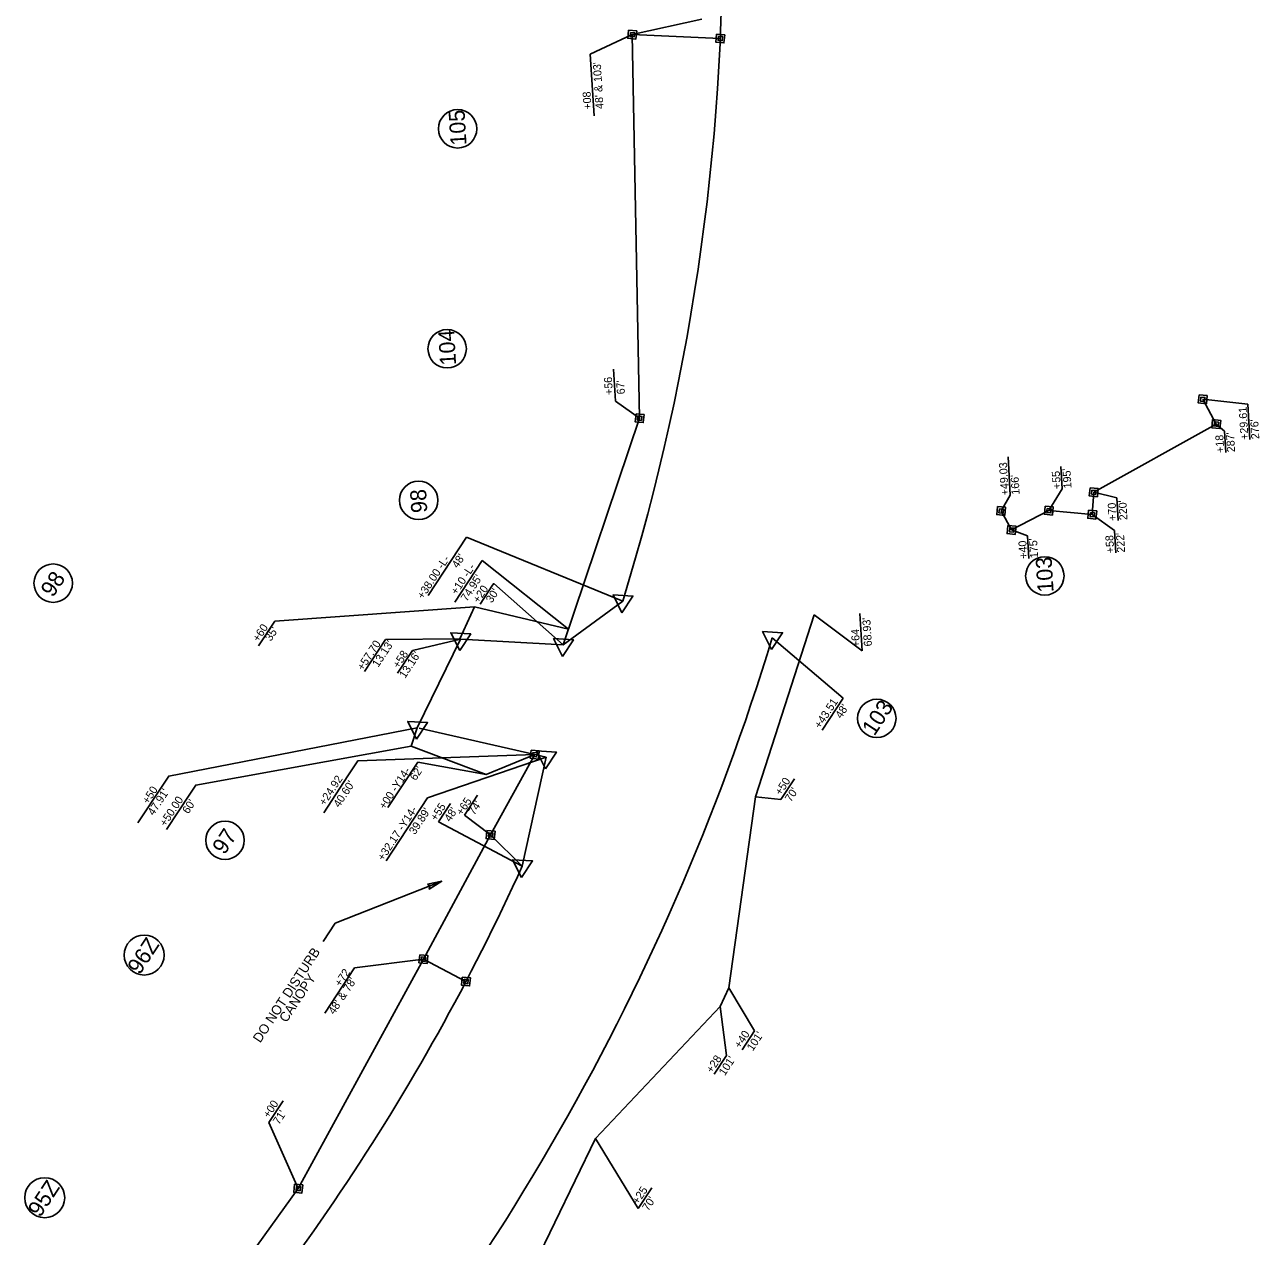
# Model space of a CAD drawing. Extents: x 2320946 to 2332748, y 597838 to 612698.
# Drawn here: x 2327953 to 2328724, y 603619 to 604376 of the extents above; entities that cross this region are included whole.
import ezdxf

# ---------------------------------------------------------------- set-up
doc = ezdxf.new("R2010")
doc.units = 0
for name, color, linetype in [('Prop DSN Text', 7, 'Continuous'), ('Prop Easement Aerial Utility', 7, 'Continuous'), ('Prop Easement Construction', 7, 'Continuous'), ('Prop Easement Construction Station Offsets', 7, 'Continuous'), ('Prop Easement Permanent Drainage Utility', 7, 'Continuous'), ('Prop Easement Permanent Utility', 7, 'Continuous'), ('Prop Easement Permanent Utility Station Offsets', 7, 'Continuous'), ('Prop Parcel Number CELL', 7, 'Continuous'), ('Prop ROW Marker CELL', 7, 'Continuous'), ('Prop ROW Permanent Easement CELL', 7, 'Continuous'), ('Prop ROW RW Lines', 7, 'Continuous'), ('Prop ROW Station Offsets', 7, 'Continuous'), ('Prop Terminator CELL', 7, 'Continuous')]:
    doc.layers.add(name, color=color, linetype=linetype)

msp = doc.modelspace()

# ---------------------------------------------------------------- linework, layer by layer
at = {"layer": 'Prop DSN Text'}
for p, q in [((2328146.87, 603814.88), (2328213.37, 603840.98)), ((2328139.33, 603803.41), (2328146.87, 603814.88))]:
    msp.add_line(p, q, dxfattribs=at)
at = {"layer": 'Prop Easement Aerial Utility'}
msp.add_line((2328201.91, 603792.36), (2328243.88, 603869.93), dxfattribs=at)
at = {"layer": 'Prop Easement Construction'}
for p, q in [((2328332.38, 604369.84), (2328375.8, 604379.44)), ((2328233.88, 604012.39), (2328224.76, 603992.38)), ((2328233.88, 604012.39), (2328292.54, 603998.53)), ((2328409.26, 603893.82), (2328445.89, 604007.5)), ((2328194.27, 603925.47), (2328198.1, 603936.93)), ((2328194.27, 603925.47), (2328241.05, 603907.72)), ((2328241.05, 603907.72), (2328271.47, 603920.11)), ((2328392.7, 603774.46), (2328409.26, 603893.82)), ((2328387.23, 603762.85), (2328392.7, 603774.46)), ((2328309.42, 603680.4), (2328387.23, 603762.85)), ((2328257.65, 603573.86), (2328309.42, 603680.4))]:
    msp.add_line(p, q, dxfattribs=at)
at = {"layer": 'Prop Easement Construction Station Offsets'}
for p, q in [((2328238.61, 604041.37), (2328221.52, 604015.4)), ((2328292.54, 603998.53), (2328238.61, 604041.37)), ((2328233.88, 604012.39), (2328109.15, 604003.51)), ((2328109.15, 604003.51), (2328098.97, 603988.03)), ((2328475.99, 603984.89), (2328445.89, 604007.5)), ((2328474.58, 604008.32), (2328475.99, 603984.89)), ((2328178.33, 603992.05), (2328165.11, 603971.96)), ((2328198.36, 603915.49), (2328179.63, 603887.01)), ((2328198.36, 603915.49), (2328241.05, 603907.72)), ((2328433.73, 603905.01), (2328425.24, 603892.11)), ((2328056, 603895.49), (2328041.39, 603873.28)), ((2328425.24, 603892.11), (2328409.26, 603893.82)), ((2328408.72, 603747.6), (2328400.94, 603735.77)), ((2328391.23, 603732.21), (2328383.54, 603720.51)), ((2328336.13, 603636.65), (2328309.42, 603680.4)), ((2328344.61, 603649.55), (2328336.13, 603636.65))]:
    msp.add_line(p, q, dxfattribs=at)
for points in [[(2328178.33, 603992.05), (2328224.76, 603992.38)], [(2328056, 603895.49), (2328059.71, 603901.13), (2328194.27, 603925.47)], [(2328408.72, 603747.6), (2328392.7, 603774.46)], [(2328391.23, 603732.21), (2328387.23, 603762.85)]]:
    msp.add_lwpolyline(points, dxfattribs=at)
at = {"layer": 'Prop Easement Permanent Drainage Utility'}
for p, q in [((2328123.77, 603649.06), (2328201.91, 603792.36)), ((2328228.48, 603778.43), (2328201.91, 603792.36)), ((2328030.98, 603521), (2328123.77, 603649.06))]:
    msp.add_line(p, q, dxfattribs=at)
at = {"layer": 'Prop Easement Permanent Utility'}
for p, q in [((2328336.98, 604130.26), (2328332.38, 604369.84)), ((2328332.38, 604369.84), (2328387.33, 604367.42)), ((2328697.11, 604126.56), (2328688.64, 604142.1)), ((2328321.81, 604140.81), (2328336.98, 604130.26)), ((2328289.2, 603988.62), (2328336.98, 604130.26)), ((2328620.61, 604083.97), (2328697.11, 604126.56)), ((2328619.65, 604070.03), (2328620.61, 604083.97)), ((2328569.29, 604060.46), (2328562.78, 604072.31)), ((2328592.54, 604072.51), (2328569.29, 604060.46)), ((2328592.54, 604072.51), (2328619.65, 604070.03)), ((2328243.88, 603869.93), (2328271.47, 603920.11))]:
    msp.add_line(p, q, dxfattribs=at)
at = {"layer": 'Prop Easement Permanent Utility Station Offsets'}
for p, q in [((2328332.38, 604369.84), (2328306.15, 604357.53)), ((2328306.15, 604357.53), (2328308.46, 604319.05)), ((2328320.6, 604160.92), (2328321.81, 604140.81)), ((2328716.81, 604139.11), (2328718.14, 604116.94)), ((2328702.21, 604122.19), (2328703.02, 604108.77)), ((2328567.03, 604106.04), (2328568.46, 604082.26)), ((2328600.05, 604100.18), (2328600.89, 604086.2)), ((2328634.94, 604080.47), (2328635.79, 604066.34)), ((2328579.17, 604056.79), (2328580.02, 604042.65)), ((2328633.47, 604060.15), (2328634.31, 604046.09)), ((2328154.76, 603906.85), (2328139.62, 603883.83)), ((2328235.69, 603894.82), (2328227.51, 603882.38)), ((2328243.88, 603869.93), (2328227.51, 603882.38)), ((2328263.68, 603850.54), (2328243.88, 603869.93)), ((2328158.88, 603786.86), (2328140.36, 603758.71)), ((2328201.91, 603792.36), (2328158.88, 603786.86)), ((2328114.34, 603703.97), (2328105.38, 603690.35)), ((2328123.77, 603649.06), (2328105.38, 603690.35))]:
    msp.add_line(p, q, dxfattribs=at)
for points in [[(2328716.81, 604139.11), (2328688.64, 604142.1)], [(2328702.21, 604122.19), (2328697.11, 604126.56)], [(2328568.46, 604082.26), (2328562.78, 604072.31)], [(2328600.89, 604086.2), (2328592.54, 604072.51)], [(2328634.94, 604080.47), (2328620.61, 604083.97)], [(2328633.47, 604060.15), (2328619.65, 604070.03)], [(2328579.17, 604056.79), (2328569.29, 604060.46)], [(2328154.76, 603906.85), (2328160.91, 603916.19), (2328271.47, 603920.11)]]:
    msp.add_lwpolyline(points, dxfattribs=at)
at = {"layer": 'Prop Parcel Number CELL'}
for p, q in [((2328223.27, 604311.01), (2328223.27, 604311.01)), ((2328216.75, 604173.62), (2328216.75, 604173.62)), ((2328198.93, 604078.96), (2328198.93, 604078.96)), ((2327970.68, 604027.21), (2327970.68, 604027.21)), ((2328590.04, 604031.76), (2328590.04, 604031.76)), ((2328485.1, 603942.76), (2328485.1, 603942.76)), ((2328078, 603866.63), (2328078, 603866.63)), ((2328027.51, 603794.93), (2328027.51, 603794.93)), ((2327965.38, 603643.39), (2327965.38, 603643.39))]:
    msp.add_line(p, q, dxfattribs=at)
for centre, radius in [((2328223.27, 604311.01), 12), ((2328216.75, 604173.62), 12), ((2328198.93, 604078.96), 12), ((2328590.04, 604031.76), 12), ((2327970.68, 604027.21), 12), ((2328485.1, 603942.76), 12), ((2328078, 603866.63), 12), ((2328027.51, 603794.93), 12.49), ((2327965.38, 603643.39), 12.49)]:
    msp.add_circle(centre, radius, dxfattribs=at)
at = {"layer": 'Prop ROW Marker CELL'}
for p, q in [((2328332.38, 604369.84), (2328332.38, 604369.84)), ((2328387.33, 604367.42), (2328387.33, 604367.42)), ((2328688.64, 604142.1), (2328688.64, 604142.1)), ((2328336.98, 604130.26), (2328336.98, 604130.26)), ((2328697.11, 604126.56), (2328697.11, 604126.56)), ((2328620.61, 604083.97), (2328620.61, 604083.97)), ((2328562.78, 604072.31), (2328562.78, 604072.31)), ((2328592.54, 604072.51), (2328592.54, 604072.51)), ((2328619.65, 604070.03), (2328619.65, 604070.03)), ((2328569.29, 604060.46), (2328569.29, 604060.46)), ((2328326.37, 604015.88), (2328326.37, 604015.88)), ((2328225.06, 603992.31), (2328225.06, 603992.31)), ((2328289.2, 603988.62), (2328289.2, 603988.62)), ((2328419.76, 603993.02), (2328419.76, 603993.02)), ((2328198.1, 603936.93), (2328198.1, 603936.93)), ((2328271.47, 603920.11), (2328271.47, 603920.11)), ((2328278.58, 603918.5), (2328278.58, 603918.5)), ((2328243.88, 603869.93), (2328243.88, 603869.93)), ((2328263.68, 603850.54), (2328263.68, 603850.54)), ((2328201.91, 603792.36), (2328201.91, 603792.36)), ((2328228.48, 603778.43), (2328228.48, 603778.43)), ((2328123.77, 603649.06), (2328123.77, 603649.06))]:
    msp.add_line(p, q, dxfattribs=at)
for points in [[(2328325.94, 604008.68), (2328320.35, 604019.84), (2328332.81, 604019.12)], [(2328224.63, 603985.11), (2328219.04, 603996.27), (2328231.5, 603995.55)], [(2328419.34, 603985.82), (2328413.75, 603996.97), (2328426.21, 603996.26)], [(2328288.77, 603981.42), (2328283.18, 603992.58), (2328295.64, 603991.87)], [(2328197.68, 603929.73), (2328192.09, 603940.89), (2328204.55, 603940.18)], [(2328278.15, 603911.3), (2328272.56, 603922.46), (2328285.02, 603921.74)], [(2328263.25, 603843.34), (2328257.66, 603854.5), (2328270.12, 603853.78)]]:
    msp.add_lwpolyline(points, close=True, dxfattribs=at)
at = {"layer": 'Prop ROW Permanent Easement CELL'}
for points in [[(2328330.1, 604372.63), (2328335.17, 604372.12), (2328334.65, 604367.05), (2328329.59, 604367.57)], [(2328331.24, 604371.24), (2328333.77, 604370.98), (2328333.52, 604368.45), (2328330.98, 604368.7)], [(2328385.05, 604370.21), (2328390.11, 604369.69), (2328389.6, 604364.63), (2328384.54, 604365.14)], [(2328386.19, 604368.81), (2328388.72, 604368.56), (2328388.46, 604366.02), (2328385.93, 604366.28)], [(2328686.36, 604144.88), (2328691.42, 604144.37), (2328690.91, 604139.31), (2328685.85, 604139.82)], [(2328687.5, 604143.49), (2328690.03, 604143.23), (2328689.77, 604140.7), (2328687.24, 604140.96)], [(2328334.71, 604133.05), (2328339.77, 604132.54), (2328339.26, 604127.47), (2328334.2, 604127.98)], [(2328335.85, 604131.65), (2328338.38, 604131.4), (2328338.12, 604128.86), (2328335.59, 604129.12)], [(2328694.84, 604129.35), (2328699.9, 604128.84), (2328699.39, 604123.78), (2328694.33, 604124.29)], [(2328695.98, 604127.96), (2328698.51, 604127.7), (2328698.25, 604125.17), (2328695.72, 604125.43)], [(2328618.33, 604086.76), (2328623.4, 604086.25), (2328622.88, 604081.18), (2328617.82, 604081.7)], [(2328619.47, 604085.37), (2328622, 604085.11), (2328621.74, 604082.58), (2328619.21, 604082.83)], [(2328560.5, 604075.1), (2328565.57, 604074.59), (2328565.05, 604069.52), (2328559.99, 604070.03)], [(2328561.64, 604073.71), (2328564.17, 604073.45), (2328563.92, 604070.92), (2328561.38, 604071.17)], [(2328590.27, 604075.3), (2328595.33, 604074.79), (2328594.82, 604069.72), (2328589.75, 604070.23)], [(2328591.4, 604073.9), (2328593.94, 604073.65), (2328593.68, 604071.12), (2328591.15, 604071.37)], [(2328617.37, 604072.82), (2328622.44, 604072.31), (2328621.92, 604067.24), (2328616.86, 604067.76)], [(2328618.51, 604071.43), (2328621.04, 604071.17), (2328620.78, 604068.64), (2328618.25, 604068.89)], [(2328567.01, 604063.24), (2328572.08, 604062.73), (2328571.56, 604057.67), (2328566.5, 604058.18)], [(2328568.15, 604061.85), (2328570.68, 604061.59), (2328570.43, 604059.06), (2328567.89, 604059.32)], [(2328269.2, 603922.9), (2328274.26, 603922.39), (2328273.75, 603917.32), (2328268.68, 603917.83)], [(2328270.33, 603921.5), (2328272.87, 603921.25), (2328272.61, 603918.72), (2328270.08, 603918.97)], [(2328241.61, 603872.72), (2328246.67, 603872.21), (2328246.16, 603867.14), (2328241.1, 603867.65)], [(2328242.75, 603871.32), (2328245.28, 603871.07), (2328245.02, 603868.54), (2328242.49, 603868.79)], [(2328199.63, 603795.15), (2328204.7, 603794.63), (2328204.18, 603789.57), (2328199.12, 603790.08)], [(2328200.77, 603793.75), (2328203.3, 603793.5), (2328203.05, 603790.96), (2328200.51, 603791.22)], [(2328226.2, 603781.22), (2328231.27, 603780.71), (2328230.76, 603775.64), (2328225.69, 603776.16)], [(2328227.34, 603779.83), (2328229.87, 603779.57), (2328229.62, 603777.04), (2328227.09, 603777.29)], [(2328121.49, 603651.85), (2328126.56, 603651.34), (2328126.05, 603646.27), (2328120.98, 603646.78)], [(2328122.63, 603650.46), (2328125.16, 603650.2), (2328124.91, 603647.67), (2328122.38, 603647.92)]]:
    msp.add_lwpolyline(points, close=True, dxfattribs=at)
at = {"layer": 'Prop ROW RW Lines'}
for p, q in [((2328326.37, 604015.88), (2328289.2, 603988.62)), ((2328198.1, 603936.93), (2328225.06, 603992.31)), ((2328225.06, 603992.31), (2328289.2, 603988.62)), ((2328271.47, 603920.11), (2328199.36, 603936.65)), ((2328271.47, 603920.11), (2328278.58, 603918.48))]:
    msp.add_line(p, q, dxfattribs=at)
msp.add_lwpolyline([(2328263.68, 603850.54), (2328278.58, 603918.48)], dxfattribs=at)
for radius, start, end in [(1402, 342.85206, 1.41227), (1498, 316.52652, 343.06963), (1402, 316.52652, 335.62094)]:
    msp.add_arc((2326986.69, 604429.25), radius, start, end, dxfattribs=at)
at = {"layer": 'Prop ROW Station Offsets'}
for p, q in [((2328228.91, 604055.93), (2328204.93, 604019.49)), ((2328228.91, 604055.93), (2328326.37, 604015.88)), ((2328245.16, 604025.93), (2328237.38, 604014.1)), ((2328195.12, 603985.18), (2328185.78, 603970.99)), ((2328464.01, 603955.36), (2328450.89, 603935.41)), ((2328204.53, 603893.08), (2328278.58, 603918.48)), ((2328038.71, 603900.44), (2328023.57, 603877.42)), ((2328204.53, 603893.08), (2328178.69, 603853.81)), ((2328218.88, 603889.52), (2328211.44, 603878.19)), ((2328211.44, 603878.19), (2328263.68, 603850.54))]:
    msp.add_line(p, q, dxfattribs=at)
for points in [[(2328245.16, 604025.93), (2328245.87, 604027), (2328289.2, 603988.62)], [(2328195.12, 603985.18), (2328225.06, 603992.31)], [(2328464.01, 603955.36), (2328419.76, 603993.02)], [(2328038.71, 603900.44), (2328042.83, 603906.71), (2328198.1, 603936.93)]]:
    msp.add_lwpolyline(points, dxfattribs=at)
at = {"layer": 'Prop Terminator CELL'}
msp.add_lwpolyline([(2328204.43, 603839.14), (2328213.37, 603840.98), (2328205.53, 603836.18), (2328206.02, 603838.09)], close=True, dxfattribs=at)

# ---------------------------------------------------------------- texts
at = {"layer": 'Prop DSN Text'}
for s, p in [('DO NOT DISTURB ', (2328100, 603739.69)), ('CANOPY', (2328116.41, 603752.36))]:
    msp.add_text(s, height=6, rotation=56.661, dxfattribs=at).set_placement(p)
at = {"layer": 'Prop Easement Construction Station Offsets'}
for s, rotation, p in [('+10 -L-', 56.66152, (2328222.75, 604019.54)), ("74.95'", 56.66152, (2328229.02, 604015.42)), ("68.93'", 93.43771, (2328482.07, 603987.86)), ('+60 ', 56.66152, (2328098.95, 603990.16)), ("35'", 56.66152, (2328106.68, 603990.54)), ('+64', 93.43771, (2328474.58, 603987.41)), ('+57.70', 56.66152, (2328164.22, 603972.2)), ("13.13'", 56.66152, (2328173.69, 603974.31)), ('+00 -Y14-', 56.66152, (2328177.83, 603885.47)), ("62'", 56.66152, (2328197.15, 603903.47)), ('+50', 56.66152, (2328425.17, 603894.27)), ("70'", 56.66152, (2328431.43, 603890.14)), ('+50.00', 56.66152, (2328040.88, 603874.78)), ("60' ", 56.66152, (2328055.09, 603882.74)), ('+40', 56.66152, (2328399.74, 603736.21)), ("101'", 56.66152, (2328407.66, 603734.6)), ('+28', 56.66152, (2328382.25, 603720.83)), ("101'", 56.66152, (2328390.16, 603719.21)), ('+25', 56.66152, (2328336.05, 603638.81)), ("70'", 56.66152, (2328342.31, 603634.69))]:
    msp.add_text(s, height=5, rotation=rotation, dxfattribs=at).set_placement(p)
at = {"layer": 'Prop Easement Permanent Utility Station Offsets'}
for s, rotation, p in [("48' & 103'", 93.43849, (2328314.45, 604323.56)), ('+08', 93.43849, (2328306.96, 604323.11)), ('+56', 93.43849, (2328320.31, 604144.86)), ("67'", 93.43849, (2328327.8, 604145.31)), ('+29.61', 93.43684, (2328717.27, 604116.89)), ("276'", 93.43684, (2328724.01, 604117.29)), ('+18', 93.43684, (2328702.14, 604108.71)), ("287'", 93.43684, (2328708.88, 604109.12)), ('+49.03', 93.43684, (2328567.58, 604082.21)), ('+55', 93.43684, (2328600.01, 604086.15)), ("195'", 93.43684, (2328606.75, 604086.56)), ("166'", 93.43684, (2328574.32, 604082.62)), ('+70', 93.43684, (2328634.92, 604066.28)), ("220'", 93.43684, (2328641.66, 604066.69)), ('+58', 93.43684, (2328633.44, 604046.04)), ("222'", 93.43684, (2328640.18, 604046.44)), ('+40', 93.43684, (2328579.15, 604042.6)), ("175'", 93.43684, (2328585.88, 604043.01)), ('+24.92', 56.66152, (2328140.38, 603887.82)), ("40.60'", 56.66152, (2328149.38, 603886.72)), ('+65', 56.66152, (2328226.08, 603881.7)), ("74'", 56.66152, (2328233.7, 603881.92)), ("48' & 78'", 56.66152, (2328146.24, 603757.43)), ('+72', 56.66152, (2328150.16, 603774.75)), ('+00', 56.66152, (2328105.44, 603692.72)), ("71'", 56.66152, (2328111.71, 603688.6))]:
    msp.add_text(s, height=5, rotation=rotation, dxfattribs=at).set_placement(p)
at = {"layer": 'Prop Parcel Number CELL'}
for s, rotation, p in [('105', 93.43684, (2328228.89, 604300.86)), ('104', 93.43684, (2328222.36, 604163.55)), ('98', 93.43684, (2328204.39, 604071.37)), ('103', 93.43849, (2328595.56, 604021.65)), ('98', 56.65986, (2327970.52, 604017.86)), ('103', 56.65986, (2328483.53, 603931.29)), ('97', 56.65986, (2328077.7, 603857.09)), ('96Z', 56.65986, (2328024.72, 603782.2)), ('95Z', 56.65986, (2327962.58, 603630.65))]:
    msp.add_text(s, height=10, rotation=rotation, dxfattribs=at).set_placement(p)
at = {"layer": 'Prop ROW Station Offsets'}
for s, rotation, p in [('+38.00 -L-', 56.66152, (2328201.7, 604016.86)), ("48'", 56.66152, (2328223.38, 604036.16)), ('+20', 56.66152, (2328236.48, 604014.33)), ("30'", 56.66152, (2328244.63, 604014.44)), ('+58', 56.66152, (2328186.45, 603973.59)), ("13.16'", 56.66152, (2328190.47, 603967.43)), ('+43.51', 56.661, (2328449.76, 603935.96)), ("48'", 56.661, (2328462.88, 603942.27)), ('+50', 56.66152, (2328030.03, 603888.84)), ("47.91'", 56.66152, (2328033.41, 603881.69)), ('+32.17 -Y14-', 56.66152, (2328176.93, 603853.41)), ("39.89'", 56.66152, (2328196.64, 603869.72)), ('+55', 56.66152, (2328209.98, 603878.26)), ("48'", 56.66152, (2328218.65, 603877.78))]:
    msp.add_text(s, height=5, rotation=rotation, dxfattribs=at).set_placement(p)

doc.saveas('drawing.dxf')
